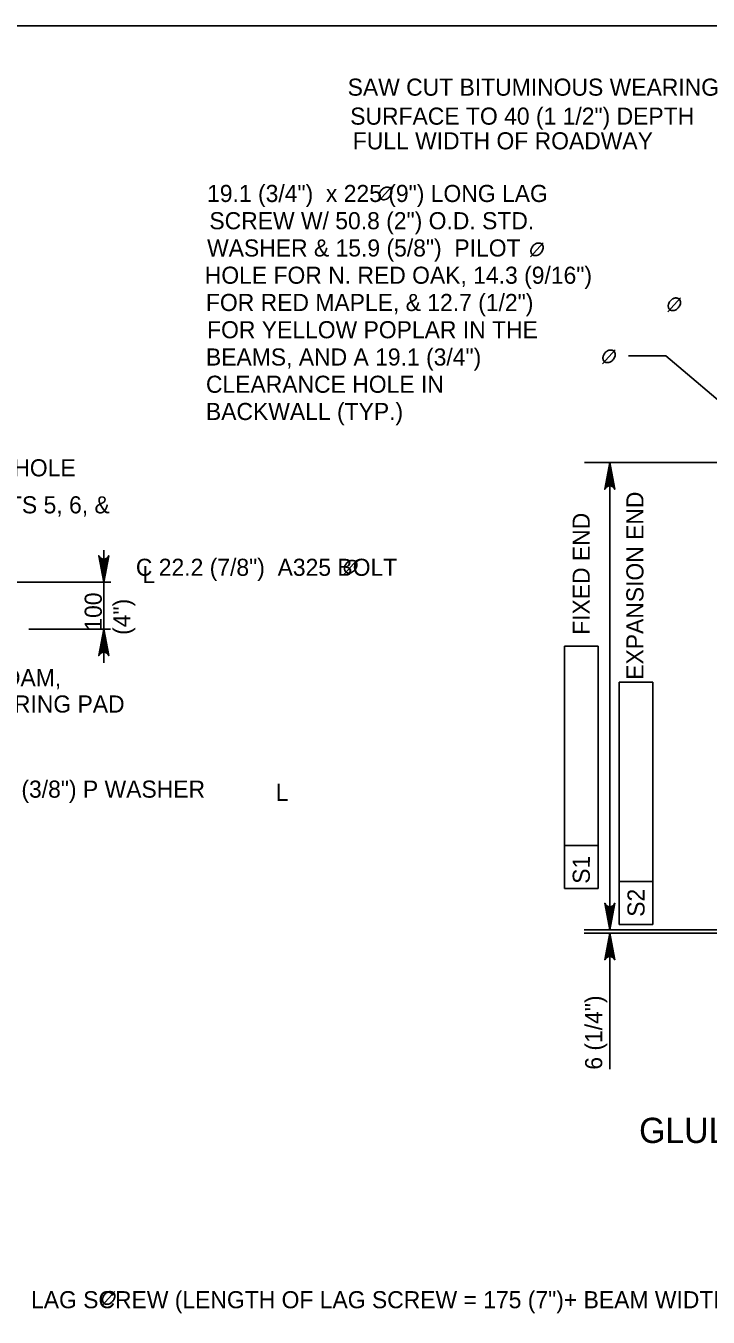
# Model space of a CAD drawing. Extents: x -13 to 81, y -176 to 0.
# Drawn here: x 43 to 47.78, y -31.81 to -22.75 of the extents above; entities that cross this region are included whole.
import ezdxf

# ---------------------------------------------------------------- set-up
doc = ezdxf.new("R2010")
doc.units = 0
for name, color, linetype in [('Level 1', 7, 'Continuous'), ('Level 3', 7, 'Continuous'), ('Level 4', 7, 'Continuous'), ('Level 8', 7, 'Continuous')]:
    doc.layers.add(name, color=color, linetype=linetype)

msp = doc.modelspace()

# ---------------------------------------------------------------- linework, layer by layer
at = {"layer": 'Level 1'}
msp.add_lwpolyline([(35.75, -43.25), (67.25, -43.25), (67.25, -22.75), (35.75, -22.75)], close=True, dxfattribs=at)
at = {"layer": 'Level 3'}
for p, q in [((47.4889, -25.0643), (47.2273, -25.0643)), ((48.273, -25.7322), (47.4889, -25.0643)), ((48.7912, -25.8148), (46.9179, -25.8148)), ((47.0951, -29.0929), (47.0951, -25.8148)), ((43.5482, -27.1878), (43.5482, -26.429)), ((38.9359, -26.6542), (43.5968, -26.6542)), ((43.022, -26.9823), (43.5951, -26.9823)), ((43.5482, -27.1004), (43.5482, -27.2185)), ((46.777, -27.1022), (47.0132, -27.1022)), ((46.777, -28.5005), (46.777, -27.1022)), ((47.0132, -28.8029), (47.0132, -27.1022)), ((47.1608, -27.3547), (47.3971, -27.3547)), ((47.1608, -28.7531), (47.1608, -27.3547)), ((47.3971, -29.0555), (47.3971, -27.3547)), ((46.777, -28.8029), (46.777, -28.5005)), ((46.777, -28.5005), (47.0132, -28.5005)), ((46.777, -28.8029), (47.0132, -28.8029)), ((47.1608, -29.0555), (47.1608, -28.7531)), ((47.1608, -28.7531), (47.3971, -28.7531)), ((47.1608, -29.0555), (47.3971, -29.0555)), ((48.2835, -29.0929), (46.9178, -29.0929))]:
    msp.add_line(p, q, dxfattribs=at)
for points in [[(47.0951, -25.8148), (47.13, -26.0012), (47.1201, -25.9868), (47.1076, -25.9794), (47.0951, -25.9772), (47.0826, -25.9794), (47.0701, -25.9868), (47.0602, -26.0012), (47.0951, -25.8148), (47.0701, -25.9868), (47.0826, -25.9794), (47.0951, -25.8148), (47.0951, -25.9772), (47.1076, -25.9794), (47.0951, -25.8148), (47.1201, -25.9868)], [(43.5482, -26.6542), (43.5132, -26.4678), (43.5232, -26.4822), (43.5357, -26.4896), (43.5482, -26.4917), (43.5607, -26.4896), (43.5732, -26.4822), (43.5831, -26.4678), (43.5482, -26.6542), (43.5732, -26.4822), (43.5607, -26.4896), (43.5482, -26.6542), (43.5482, -26.4917), (43.5357, -26.4896), (43.5482, -26.6542), (43.5232, -26.4822)], [(43.5482, -26.9823), (43.5831, -27.1687), (43.5732, -27.1544), (43.5607, -27.147), (43.5482, -27.1448), (43.5357, -27.147), (43.5232, -27.1544), (43.5132, -27.1687), (43.5482, -26.9823), (43.5232, -27.1544), (43.5357, -27.147), (43.5482, -26.9823), (43.5482, -27.1448), (43.5607, -27.147), (43.5482, -26.9823), (43.5732, -27.1544)], [(47.0951, -29.0929), (47.0602, -28.9065), (47.0701, -28.9208), (47.0826, -28.9282), (47.0951, -28.9304), (47.1076, -28.9282), (47.1201, -28.9208), (47.13, -28.9065), (47.0951, -29.0929), (47.1201, -28.9208), (47.1076, -28.9282), (47.0951, -29.0929), (47.0951, -28.9304), (47.0826, -28.9282), (47.0951, -29.0929), (47.0701, -28.9208)], [(47.0951, -29.1164), (47.13, -29.3028), (47.1201, -29.2885), (47.1076, -29.2811), (47.0951, -29.2789), (47.0826, -29.2811), (47.0701, -29.2885), (47.0602, -29.3028), (47.0951, -29.1164), (47.0701, -29.2885), (47.0826, -29.2811), (47.0951, -29.1164), (47.0951, -29.2789), (47.1076, -29.2811), (47.0951, -29.1164), (47.1201, -29.2885)]]:
    msp.add_lwpolyline(points, dxfattribs=at)
at = {"layer": 'Level 4'}
for p, q in [((45.4765, -23.9785), (45.5661, -23.8804)), ((46.5392, -24.3705), (46.6287, -24.2724)), ((47.5022, -24.7559), (47.5917, -24.6578)), ((47.0439, -25.1213), (47.1335, -25.0233)), ((45.2322, -26.5981), (45.3218, -26.5)), ((43.5367, -31.7276), (43.6262, -31.6295))]:
    msp.add_line(p, q, dxfattribs=at)
for points in [[(45.5568, -23.8901), (45.5497, -23.8847), (45.5427, -23.8827), (45.5341, -23.882), (45.5289, -23.882), (45.5204, -23.8839), (45.5124, -23.8876), (45.507, -23.8907), (45.4964, -23.8992), (45.4881, -23.9099), (45.4831, -23.92), (45.4802, -23.9292), (45.4793, -23.9379), (45.4802, -23.9452), (45.4838, -23.9558), (45.4877, -23.9612), (45.4952, -23.9672), (45.5068, -23.9699), (45.5201, -23.9695), (45.5368, -23.9618), (45.549, -23.9514), (45.5582, -23.9387), (45.5642, -23.9254), (45.5662, -23.9108), (45.5636, -23.9012), (45.5572, -23.8901)], [(46.6195, -24.2821), (46.6124, -24.2767), (46.6054, -24.2748), (46.5968, -24.274), (46.5916, -24.274), (46.5831, -24.2759), (46.5751, -24.2796), (46.5697, -24.2827), (46.5591, -24.2912), (46.5508, -24.3019), (46.5457, -24.312), (46.5428, -24.3212), (46.5419, -24.3299), (46.5428, -24.3373), (46.5465, -24.3478), (46.5503, -24.3532), (46.5579, -24.3592), (46.5695, -24.3619), (46.5827, -24.3615), (46.5995, -24.3538), (46.6117, -24.3434), (46.6208, -24.3307), (46.6268, -24.3174), (46.6288, -24.3027), (46.6262, -24.2933), (46.6199, -24.2821)], [(47.5825, -24.6675), (47.5754, -24.6621), (47.5684, -24.6602), (47.5598, -24.6594), (47.5546, -24.6594), (47.5461, -24.6613), (47.5381, -24.665), (47.5327, -24.6681), (47.5221, -24.6766), (47.5138, -24.6873), (47.5087, -24.6974), (47.5058, -24.7067), (47.5049, -24.7153), (47.5058, -24.7227), (47.5095, -24.7332), (47.5133, -24.7387), (47.5209, -24.7446), (47.5325, -24.7473), (47.5457, -24.7469), (47.5625, -24.7392), (47.5747, -24.7288), (47.5838, -24.7161), (47.5898, -24.7028), (47.5918, -24.6882), (47.5892, -24.6787), (47.5829, -24.6675)], [(47.1242, -25.0329), (47.1172, -25.0275), (47.1102, -25.0256), (47.1015, -25.0248), (47.0963, -25.0248), (47.0878, -25.0267), (47.0798, -25.0304), (47.0744, -25.0335), (47.0638, -25.042), (47.0555, -25.0527), (47.0505, -25.0628), (47.0476, -25.0721), (47.0467, -25.0807), (47.0476, -25.0881), (47.0512, -25.0987), (47.0551, -25.1041), (47.0627, -25.11), (47.0742, -25.1127), (47.0875, -25.1123), (47.1043, -25.1047), (47.1164, -25.0942), (47.1256, -25.0815), (47.1316, -25.0682), (47.1336, -25.0536), (47.131, -25.0441), (47.1247, -25.0329)], [(45.3125, -26.5097), (45.3054, -26.5042), (45.2984, -26.5023), (45.2897, -26.5016), (45.2846, -26.5016), (45.2761, -26.5035), (45.2681, -26.5072), (45.2627, -26.5102), (45.2521, -26.5188), (45.2437, -26.5295), (45.2387, -26.5396), (45.2358, -26.5488), (45.2349, -26.5575), (45.2358, -26.5648), (45.2395, -26.5754), (45.2433, -26.5808), (45.2509, -26.5867), (45.2625, -26.5895), (45.2757, -26.5891), (45.2925, -26.5814), (45.3047, -26.571), (45.3138, -26.5582), (45.3198, -26.545), (45.3218, -26.5303), (45.3192, -26.5208), (45.3129, -26.5097)], [(43.617, -31.6392), (43.6099, -31.6337), (43.6029, -31.6318), (43.5942, -31.6311), (43.5891, -31.6311), (43.5806, -31.633), (43.5726, -31.6367), (43.5672, -31.6397), (43.5566, -31.6482), (43.5482, -31.659), (43.5433, -31.6691), (43.5403, -31.6783), (43.5394, -31.687), (43.5403, -31.6943), (43.544, -31.7049), (43.5478, -31.7103), (43.5554, -31.7162), (43.567, -31.719), (43.5802, -31.7186), (43.597, -31.7109), (43.6092, -31.7005), (43.6183, -31.6877), (43.6243, -31.6745), (43.6263, -31.6598), (43.6238, -31.6503), (43.6174, -31.6392)]]:
    msp.add_spline(points, degree=3, dxfattribs=at)
at = {"layer": 'Level 8'}
for p, q in [((47.0951, -28.9729), (47.0951, -28.8529)), ((48.2675, -29.1164), (46.915, -29.1164)), ((48.9557, -29.0929), (46.9151, -29.0929)), ((47.0951, -29.1164), (47.0951, -30.0693))]:
    msp.add_line(p, q, dxfattribs=at)

# ---------------------------------------------------------------- texts
at = {"layer": 'Level 3'}
for s, height, p in [('SAW CUT BITUMINOUS WEARING', 0.12, (45.2576, -23.2403)), ('SURFACE TO 40 (1 1/2") DEPTH', 0.12, (45.2755, -23.4436)), ('FULL WIDTH OF ROADWAY', 0.12, (45.2934, -23.6167)), ('19.1 (3/4")  x 225 (9") LONG LAG ', 0.12, (44.2723, -23.9861)), ('SCREW W/ 50.8 (2") O.D. STD. ', 0.12, (44.2884, -24.1773)), ('WASHER & 15.9 (5/8")  PILOT ', 0.12, (44.2723, -24.3685)), ('HOLE FOR N. RED OAK, 14.3 (9/16")  ', 0.12, (44.2563, -24.5597)), ('FOR RED MAPLE, & 12.7 (1/2")  ', 0.12, (44.2643, -24.751)), ('FOR YELLOW POPLAR IN THE', 0.12, (44.2723, -24.9422)), ('BEAMS, AND A 19.1 (3/4") ', 0.12, (44.2643, -25.1335)), ('CLEARANCE HOLE IN', 0.12, (44.2643, -25.3247)), ('BACKWALL (TYP.)', 0.12, (44.2643, -25.5159)), ('BEARING P (SEE BLC-562M SHEETS 5, 6, & ', 0.12, (40.2904, -26.1707)), ('C 22.2 (7/8")  A325 BOLT', 0.12, (43.7731, -26.6089)), ('L', 0.12, (43.8181, -26.6598)), ('FILL VOID UNDER P W/ STYROFOAM,', 0.12, (40.3787, -27.3834)), ('5 mm (3/16") THICKER THAN BEARING PAD', 0.12, (40.4005, -27.5682)), ('19.1 (3/4")  LAG SCREW W/ 10 (3/8") P WASHER', 0.12, (40.6664, -28.1655)), ('L', 0.12, (44.7536, -28.1876)), ('GLULAM BACKWALL DETAIL', 0.177167, (47.3004, -30.5882)), ('L 19.1 (3/4")  LAG SCREW (LENGTH OF LAG SCREW = 175 (7")+ BEAM WIDTH)', 0.12, (42.0714, -31.7477))]:
    msp.add_text(s, height=height, dxfattribs=at).set_placement(p)
for s, rotation, p in [('EXPANSION END', 90, (47.3312, -27.3378)), ('FIXED END', 90, (46.9545, -27.0225)), ('100', 90, (43.5341, -26.9936)), ('(4")', 90, (43.7341, -27.0232)), ('S1', 89.93823, (46.955, -28.7695)), ('S2', 89.93823, (47.3388, -29.0011)), ('6 (1/4")', 90, (47.042, -30.0738))]:
    msp.add_text(s, height=0.12, rotation=rotation, dxfattribs=at).set_placement(p)
at = {"layer": 'Level 4'}
msp.add_text('23.8x28.6 (15/16"x1 1/8") VERT. SLOTTED HOLE', height=0.12, dxfattribs=at).set_placement((39.7587, -25.911))

doc.saveas('drawing.dxf')
